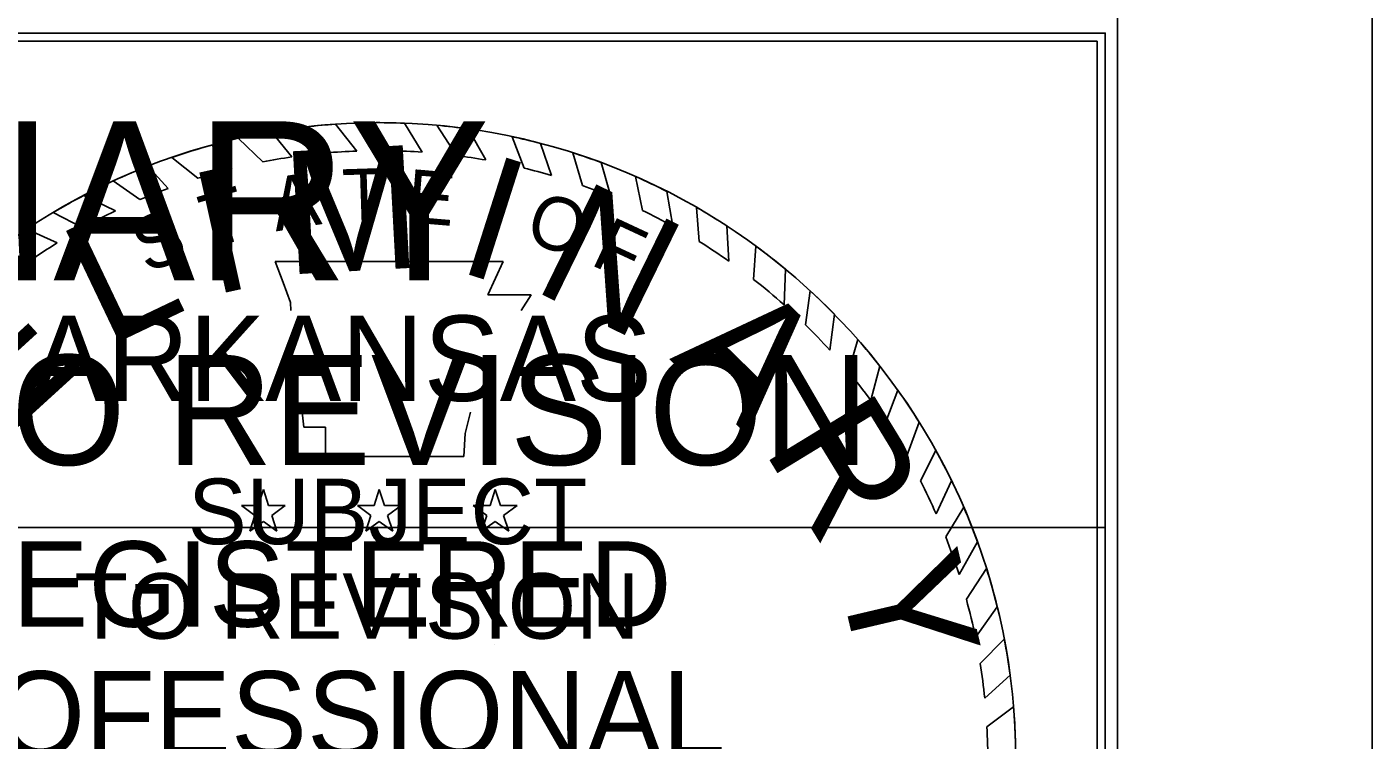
# Model space of a CAD drawing. Extents: x -0.29 to 1.42, y 0 to 0.92.
# Drawn here: x 1.3066 to 1.4167, y 0.7945 to 0.8529 of the extents above; entities that cross this region are included whole.
import ezdxf

# ---------------------------------------------------------------- set-up
doc = ezdxf.new("R2010")
doc.units = 0
for name, color, linetype in [('DSN_DRFT_Guideline-No-Plot', 7, 'Continuous'), ('SHET_Border-Lines', 7, 'Continuous'), ('SHET_Stamp-Prelim', 7, 'Continuous'), ('SHET_Stamp-Seal', 7, 'Continuous'), ('STAMP_PE_BACKGROUND', 7, 'Continuous'), ('STAMP_PE_SEAL-INFO', 7, 'Continuous'), ('STAMP_PRELIMINARY', 7, 'Continuous')]:
    doc.layers.add(name, color=color, linetype=linetype)

msp = doc.modelspace()

# ---------------------------------------------------------------- linework, layer by layer
at = {"layer": 'DSN_DRFT_Guideline-No-Plot'}
msp.add_lwpolyline([(0, 0), (1.416666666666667, 0), (1.416666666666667, 0.9166666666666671), (0, 0.9166666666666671)], close=True, dxfattribs=at)
at = {"layer": 'SHET_Border-Lines'}
msp.add_lwpolyline([(0.02083333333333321, 0.02083333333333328), (1.3958333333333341, 0.02083333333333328), (1.3958333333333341, 0.8958333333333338), (0.02083333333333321, 0.8958333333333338)], close=True, dxfattribs=at)
at = {"layer": 'SHET_Stamp-Prelim'}
msp.add_lwpolyline([(1.2136619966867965, 0.8119287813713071), (1.3948333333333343, 0.8119287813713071), (1.3948333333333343, 0.8523810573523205), (1.2136619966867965, 0.8523810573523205)], close=True, dxfattribs=at)
at = {"layer": 'SHET_Stamp-Seal'}
msp.add_line((1.3448333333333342, 0.8023810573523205), (1.3448333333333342, 0.8023810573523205), dxfattribs=at)
msp.add_lwpolyline([(1.2948333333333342, 0.7523810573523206), (1.3948333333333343, 0.7523810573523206), (1.3948333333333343, 0.8523810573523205), (1.2948333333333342, 0.8523810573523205)], close=True, dxfattribs=at)
at = {"layer": 'STAMP_PE_BACKGROUND'}
msp.add_lwpolyline([(1.3941666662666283, 0.8517143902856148), (1.2749999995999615, 0.8517143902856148), (1.2749999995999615, 0.7325477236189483), (1.3941666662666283, 0.7325477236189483)], close=True, dxfattribs=at)
msp.add_lwpolyline([(1.3941666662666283, 0.8517143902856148), (1.2749999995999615, 0.8517143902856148), (1.2749999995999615, 0.7325477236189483), (1.3941666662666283, 0.7325477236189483)], close=True, dxfattribs=at)
at = {"layer": 'STAMP_PE_SEAL-INFO'}
for p, q in [((1.3294739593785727, 0.8447075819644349), (1.3310448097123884, 0.8425694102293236)), ((1.3294739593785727, 0.8447075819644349), (1.3310448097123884, 0.8425694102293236)), ((1.3335830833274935, 0.8427279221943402), (1.3318396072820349, 0.8449247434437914)), ((1.3335830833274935, 0.8427279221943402), (1.3318396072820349, 0.8449247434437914)), ((1.3363642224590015, 0.8427526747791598), (1.3348070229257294, 0.8450441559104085)), ((1.3363642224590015, 0.8427526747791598), (1.3348070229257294, 0.8450441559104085)), ((1.338922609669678, 0.8426381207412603), (1.337479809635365, 0.8450068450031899)), ((1.338922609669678, 0.8426381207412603), (1.337479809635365, 0.8450068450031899)), ((1.3417476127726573, 0.8423576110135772), (1.3401157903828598, 0.8448353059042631)), ((1.3417476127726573, 0.8423576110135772), (1.3401157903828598, 0.8448353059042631)), ((1.3441268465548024, 0.8419940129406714), (1.342689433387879, 0.8445374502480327)), ((1.3441268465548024, 0.8419940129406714), (1.342689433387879, 0.8445374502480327)), ((1.3238985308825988, 0.843758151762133), (1.3258868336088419, 0.8418413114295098)), ((1.3238985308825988, 0.843758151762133), (1.3258868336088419, 0.8418413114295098)), ((1.3265941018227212, 0.8442950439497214), (1.3282642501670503, 0.8422453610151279)), ((1.3265941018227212, 0.8442950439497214), (1.3282642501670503, 0.8422453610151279)), ((1.3472684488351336, 0.8413307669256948), (1.346296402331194, 0.8438987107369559)), ((1.3472684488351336, 0.8413307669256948), (1.346296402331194, 0.8438987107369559)), ((1.3495119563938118, 0.8407251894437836), (1.348622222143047, 0.843345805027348)), ((1.3495119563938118, 0.8407251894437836), (1.348622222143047, 0.843345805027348)), ((1.3184297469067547, 0.8421997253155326), (1.3205571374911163, 0.8404929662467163)), ((1.3184297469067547, 0.8421997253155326), (1.3205571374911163, 0.8404929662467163)), ((1.3217312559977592, 0.8432175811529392), (1.3233399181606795, 0.841275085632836)), ((1.3217312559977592, 0.8432175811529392), (1.3233399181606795, 0.841275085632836)), ((1.352036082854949, 0.8399065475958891), (1.3512467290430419, 0.8425837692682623)), ((1.352036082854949, 0.8399065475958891), (1.3512467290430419, 0.8425837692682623)), ((1.3164868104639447, 0.8414858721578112), (1.3181331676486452, 0.8396661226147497)), ((1.3164868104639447, 0.8414858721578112), (1.3181331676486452, 0.8396661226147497)), ((1.3543729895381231, 0.8390125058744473), (1.3535662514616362, 0.8417830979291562)), ((1.3543729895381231, 0.8390125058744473), (1.3535662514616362, 0.8417830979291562)), ((1.3136506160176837, 0.8402815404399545), (1.3158266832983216, 0.8387465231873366)), ((1.3136506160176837, 0.8402815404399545), (1.3158266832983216, 0.8387465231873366)), ((1.356950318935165, 0.8378650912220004), (1.3563760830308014, 0.8406443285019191)), ((1.356950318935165, 0.8378650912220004), (1.3563760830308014, 0.8406443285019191)), ((1.3112428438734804, 0.8390978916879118), (1.3138318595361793, 0.8378405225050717)), ((1.3112428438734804, 0.8390978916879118), (1.3138318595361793, 0.8378405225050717)), ((1.3594403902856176, 0.8365835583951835), (1.3589543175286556, 0.8394256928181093)), ((1.3594403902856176, 0.8365835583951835), (1.3589543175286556, 0.8394256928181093)), ((1.3616057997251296, 0.8353188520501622), (1.3613841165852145, 0.8381126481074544)), ((1.3616057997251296, 0.8353188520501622), (1.3613841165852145, 0.8381126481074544)), ((1.3087400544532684, 0.8376972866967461), (1.3111542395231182, 0.8364512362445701)), ((1.3087400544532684, 0.8376972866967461), (1.3111542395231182, 0.8364512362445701)), ((1.3065791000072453, 0.8363356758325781), (1.3090468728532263, 0.8352066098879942)), ((1.3065791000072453, 0.8363356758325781), (1.3090468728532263, 0.8352066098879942)), ((1.3640334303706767, 0.8337179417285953), (1.3638592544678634, 0.8365957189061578)), ((1.3640334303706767, 0.8337179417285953), (1.3638592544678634, 0.8365957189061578)), ((1.304230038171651, 0.834845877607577), (1.3067758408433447, 0.8337010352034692)), ((1.304230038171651, 0.834845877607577), (1.3067758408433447, 0.8337010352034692)), ((1.3660478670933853, 0.8322263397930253), (1.3662390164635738, 0.8349483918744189)), ((1.3660478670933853, 0.8322263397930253), (1.3662390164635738, 0.8349483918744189)), ((1.3268852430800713, 0.8336989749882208), (1.3455681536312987, 0.8336989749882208)), ((1.3275632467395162, 0.831981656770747), (1.3268852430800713, 0.8336989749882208)), ((1.3268852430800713, 0.8336989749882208), (1.3455681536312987, 0.8336989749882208)), ((1.3275632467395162, 0.831981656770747), (1.3268852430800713, 0.8336989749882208)), ((1.3455681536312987, 0.8336989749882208), (1.3443118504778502, 0.8309512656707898)), ((1.3455681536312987, 0.8336989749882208), (1.3443118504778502, 0.8309512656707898)), ((1.3685422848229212, 0.8301458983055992), (1.368651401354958, 0.833065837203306)), ((1.3685422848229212, 0.8301458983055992), (1.368651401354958, 0.833065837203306)), ((1.3281440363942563, 0.830318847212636), (1.3275632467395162, 0.831981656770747)), ((1.3281440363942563, 0.830318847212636), (1.3275632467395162, 0.831981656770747)), ((1.3702883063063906, 0.8285135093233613), (1.370675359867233, 0.8312984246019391)), ((1.3702883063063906, 0.8285135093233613), (1.370675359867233, 0.8312984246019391)), ((1.3281841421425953, 0.8296795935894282), (1.3281440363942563, 0.830318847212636)), ((1.3281841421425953, 0.8296795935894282), (1.3281440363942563, 0.830318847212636)), ((1.3443118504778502, 0.8309512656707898), (1.3478453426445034, 0.8309512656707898)), ((1.3443118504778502, 0.8309512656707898), (1.3478453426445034, 0.8309512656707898)), ((1.3478453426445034, 0.8309512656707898), (1.3470357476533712, 0.8296795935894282)), ((1.3478453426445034, 0.8309512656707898), (1.3470357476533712, 0.8296795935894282)), ((1.3722943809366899, 0.8264278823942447), (1.37266661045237, 0.8293665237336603)), ((1.3722943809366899, 0.8264278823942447), (1.37266661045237, 0.8293665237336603)), ((1.3738243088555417, 0.8246601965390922), (1.374586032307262, 0.8272927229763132)), ((1.3738243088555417, 0.8246601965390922), (1.374586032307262, 0.8272927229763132)), ((1.3756344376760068, 0.8223293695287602), (1.3763889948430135, 0.82511935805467)), ((1.3756344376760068, 0.8223293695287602), (1.3763889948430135, 0.82511935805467)), ((1.376862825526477, 0.8205685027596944), (1.3778557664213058, 0.8231570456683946)), ((1.376862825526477, 0.8205685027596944), (1.3778557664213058, 0.8231570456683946)), ((1.3292525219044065, 0.8201321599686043), (1.3291057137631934, 0.8213470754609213)), ((1.3292525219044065, 0.8201321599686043), (1.3291057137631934, 0.8213470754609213)), ((1.3428700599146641, 0.8213470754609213), (1.3424349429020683, 0.8196169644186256)), ((1.3428700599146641, 0.8213470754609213), (1.3424349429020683, 0.8196169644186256)), ((1.378584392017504, 0.8177901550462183), (1.379604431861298, 0.8205345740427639)), ((1.378584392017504, 0.8177901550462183), (1.379604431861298, 0.8205345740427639)), ((1.331008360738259, 0.8201321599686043), (1.3292525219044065, 0.8201321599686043)), ((1.331008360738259, 0.8201321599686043), (1.3292525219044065, 0.8201321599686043)), ((1.331008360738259, 0.8177279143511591), (1.331008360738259, 0.8201321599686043)), ((1.331008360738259, 0.8177279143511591), (1.331008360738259, 0.8201321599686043)), ((1.3424349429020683, 0.8196169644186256), (1.3423475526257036, 0.8177279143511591)), ((1.3424349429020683, 0.8196169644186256), (1.3423475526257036, 0.8177279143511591)), ((1.3796987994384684, 0.815742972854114), (1.380964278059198, 0.8182248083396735)), ((1.3796987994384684, 0.815742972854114), (1.380964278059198, 0.8182248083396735)), ((1.3423475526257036, 0.8177279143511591), (1.331008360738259, 0.8177279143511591)), ((1.3423475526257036, 0.8177279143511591), (1.331008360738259, 0.8177279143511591)), ((1.3255072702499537, 0.8137223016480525), (1.3259305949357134, 0.8150251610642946)), ((1.3255072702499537, 0.8137223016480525), (1.3259305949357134, 0.8150251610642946)), ((1.3259305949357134, 0.8150251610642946), (1.326353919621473, 0.8137223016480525)), ((1.3259305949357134, 0.8150251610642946), (1.326353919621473, 0.8137223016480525)), ((1.3349933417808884, 0.8137223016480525), (1.3354166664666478, 0.8150251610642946)), ((1.3349933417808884, 0.8137223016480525), (1.3354166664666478, 0.8150251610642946)), ((1.3354166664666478, 0.8150251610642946), (1.3358399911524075, 0.8137223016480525)), ((1.3354166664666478, 0.8150251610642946), (1.3358399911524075, 0.8137223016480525)), ((1.344479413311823, 0.8137223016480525), (1.3449027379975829, 0.8150251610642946)), ((1.344479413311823, 0.8137223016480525), (1.3449027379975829, 0.8150251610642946)), ((1.3449027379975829, 0.8150251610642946), (1.345326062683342, 0.8137223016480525)), ((1.3449027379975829, 0.8150251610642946), (1.345326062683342, 0.8137223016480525)), ((1.380988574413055, 0.813038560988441), (1.3822531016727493, 0.815746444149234)), ((1.380988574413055, 0.813038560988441), (1.3822531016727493, 0.815746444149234)), ((1.3252456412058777, 0.812917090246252), (1.3241373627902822, 0.8137223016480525)), ((1.3241373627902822, 0.8137223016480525), (1.325507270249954, 0.8137223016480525)), ((1.3252456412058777, 0.812917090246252), (1.3241373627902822, 0.8137223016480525)), ((1.3241373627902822, 0.8137223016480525), (1.325507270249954, 0.8137223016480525)), ((1.326353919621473, 0.8137223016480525), (1.327723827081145, 0.8137223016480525)), ((1.326353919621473, 0.8137223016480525), (1.327723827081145, 0.8137223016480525)), ((1.327723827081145, 0.8137223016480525), (1.326615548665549, 0.812917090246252)), ((1.327723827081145, 0.8137223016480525), (1.326615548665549, 0.812917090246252)), ((1.3347317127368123, 0.812917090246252), (1.3336234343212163, 0.8137223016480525)), ((1.3336234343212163, 0.8137223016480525), (1.3349933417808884, 0.8137223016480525)), ((1.3347317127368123, 0.812917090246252), (1.3336234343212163, 0.8137223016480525)), ((1.3336234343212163, 0.8137223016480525), (1.3349933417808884, 0.8137223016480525)), ((1.3358399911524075, 0.8137223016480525), (1.337209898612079, 0.8137223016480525)), ((1.3358399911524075, 0.8137223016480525), (1.337209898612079, 0.8137223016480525)), ((1.337209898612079, 0.8137223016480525), (1.3361016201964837, 0.812917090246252)), ((1.337209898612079, 0.8137223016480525), (1.3361016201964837, 0.812917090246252)), ((1.3442177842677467, 0.812917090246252), (1.3431095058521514, 0.8137223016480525)), ((1.3431095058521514, 0.8137223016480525), (1.344479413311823, 0.8137223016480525)), ((1.3442177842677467, 0.812917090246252), (1.3431095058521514, 0.8137223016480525)), ((1.3431095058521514, 0.8137223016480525), (1.344479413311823, 0.8137223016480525)), ((1.345326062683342, 0.8137223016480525), (1.3466959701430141, 0.8137223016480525)), ((1.345326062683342, 0.8137223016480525), (1.3466959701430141, 0.8137223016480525)), ((1.3466959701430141, 0.8137223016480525), (1.345587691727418, 0.812917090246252)), ((1.3466959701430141, 0.8137223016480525), (1.345587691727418, 0.812917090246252)), ((1.381772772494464, 0.811154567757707), (1.3832473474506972, 0.8135774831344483)), ((1.381772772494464, 0.811154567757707), (1.3832473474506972, 0.8135774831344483)), ((1.3248223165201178, 0.81161423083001), (1.3252456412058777, 0.812917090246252)), ((1.3248223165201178, 0.81161423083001), (1.3252456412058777, 0.812917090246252)), ((1.326615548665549, 0.812917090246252), (1.327038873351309, 0.81161423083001)), ((1.326615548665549, 0.812917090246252), (1.327038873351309, 0.81161423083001)), ((1.3343083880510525, 0.81161423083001), (1.3347317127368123, 0.812917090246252)), ((1.3343083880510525, 0.81161423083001), (1.3347317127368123, 0.812917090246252)), ((1.3361016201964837, 0.812917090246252), (1.3365249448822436, 0.81161423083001)), ((1.3361016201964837, 0.812917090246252), (1.3365249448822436, 0.81161423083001)), ((1.3437944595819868, 0.81161423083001), (1.3442177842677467, 0.812917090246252)), ((1.3437944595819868, 0.81161423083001), (1.3442177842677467, 0.812917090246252)), ((1.345587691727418, 0.812917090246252), (1.346011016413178, 0.81161423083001)), ((1.345587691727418, 0.812917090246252), (1.346011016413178, 0.81161423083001)), ((1.3259305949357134, 0.8124194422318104), (1.3248223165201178, 0.81161423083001)), ((1.3259305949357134, 0.8124194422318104), (1.3248223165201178, 0.81161423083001)), ((1.327038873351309, 0.81161423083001), (1.3259305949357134, 0.8124194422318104)), ((1.327038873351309, 0.81161423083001), (1.3259305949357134, 0.8124194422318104)), ((1.3354166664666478, 0.8124194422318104), (1.3343083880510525, 0.81161423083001)), ((1.3354166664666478, 0.8124194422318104), (1.3343083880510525, 0.81161423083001)), ((1.3365249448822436, 0.81161423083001), (1.3354166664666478, 0.8124194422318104)), ((1.3365249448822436, 0.81161423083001), (1.3354166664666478, 0.8124194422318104)), ((1.3449027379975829, 0.8124194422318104), (1.3437944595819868, 0.81161423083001)), ((1.3449027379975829, 0.8124194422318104), (1.3437944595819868, 0.81161423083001)), ((1.346011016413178, 0.81161423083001), (1.3449027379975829, 0.8124194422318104)), ((1.346011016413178, 0.81161423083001), (1.3449027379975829, 0.8124194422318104)), ((1.382861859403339, 0.8080880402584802), (1.3843733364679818, 0.8107384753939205)), ((1.382861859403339, 0.8080880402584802), (1.3843733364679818, 0.8107384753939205)), ((1.3834635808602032, 0.8060512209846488), (1.3851045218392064, 0.8085781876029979)), ((1.3834635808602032, 0.8060512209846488), (1.3851045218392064, 0.8085781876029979)), ((1.3842065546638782, 0.8029302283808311), (1.3859874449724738, 0.8054251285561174)), ((1.3842065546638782, 0.8029302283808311), (1.3859874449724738, 0.8054251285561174)), ((1.384592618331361, 0.8008063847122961), (1.3865668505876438, 0.8027792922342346)), ((1.384592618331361, 0.8008063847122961), (1.3865668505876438, 0.8027792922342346)), ((1.3849625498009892, 0.797962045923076), (1.3870442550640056, 0.7998393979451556)), ((1.3849625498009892, 0.797962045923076), (1.3870442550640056, 0.7998393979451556)), ((1.3851427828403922, 0.7956260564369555), (1.3873228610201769, 0.7972563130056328)), ((1.3851427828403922, 0.7956260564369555), (1.3873228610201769, 0.7972563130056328))]:
    msp.add_line(p, q, dxfattribs=at)
for radius, start, end in [(0.05208333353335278, 93.93814766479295, 96.55171575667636), (0.05208333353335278, 93.93814766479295, 96.55171575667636), (0.05208333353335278, 87.72978562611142, 90.67067134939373), (0.05208333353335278, 87.72978562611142, 90.67067134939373), (0.05208333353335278, 81.97315125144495, 84.82355346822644), (0.05208333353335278, 81.97315125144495, 84.82355346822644), (0.05208333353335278, 99.75254266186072, 102.77648138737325), (0.05208333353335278, 99.75254266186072, 102.77648138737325), (0.05208333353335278, 75.31251453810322, 77.94263429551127), (0.05208333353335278, 75.31251453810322, 77.94263429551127), (0.05208333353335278, 105.2338868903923, 109.03519250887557), (0.05208333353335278, 105.2338868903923, 109.03519250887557), (0.04979730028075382, 98.25798851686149, 101.03289140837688), (0.04979730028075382, 98.25798851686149, 101.03289140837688), (0.04979730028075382, 92.11016115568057, 95.0366553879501), (0.04979730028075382, 92.11016115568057, 95.0366553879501), (0.04979730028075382, 85.96279180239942, 88.90969519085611), (0.04979730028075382, 85.96279180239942, 88.90969519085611), (0.04979730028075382, 79.92642235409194, 82.69597271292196), (0.04979730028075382, 79.92642235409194, 82.69597271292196), (0.05208333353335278, 69.60611387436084, 72.30576523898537), (0.05208333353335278, 69.60611387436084, 72.30576523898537), (0.05208333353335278, 111.31242303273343, 114.70259160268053), (0.05208333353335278, 111.31242303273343, 114.70259160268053), (0.04979730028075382, 104.03521042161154, 107.3615463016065), (0.04979730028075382, 104.03521042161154, 107.3615463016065), (0.04979730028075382, 73.55748025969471, 76.23144174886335), (0.04979730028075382, 73.55748025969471, 76.23144174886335), (0.05208333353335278, 63.13287778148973, 66.27039835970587), (0.05208333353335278, 63.13287778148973, 66.27039835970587), (0.05208333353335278, 117.65440981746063, 120.8098782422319), (0.05208333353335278, 117.65440981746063, 120.8098782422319), (0.04979730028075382, 110.30863674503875, 113.1658795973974), (0.04979730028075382, 110.30863674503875, 113.1658795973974), (0.04979730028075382, 67.62482877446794, 70.50398398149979), (0.04979730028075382, 67.62482877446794, 70.50398398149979), (0.04979730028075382, 115.68691928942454, 119.15826889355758), (0.04979730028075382, 115.68691928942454, 119.15826889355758), (0.04979730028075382, 61.155754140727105, 64.37837449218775), (0.04979730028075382, 61.155754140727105, 64.37837449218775), (0.05208333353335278, 56.90029228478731, 60.09422987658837), (0.05208333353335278, 56.90029228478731, 60.09422987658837), (0.04979730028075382, 121.97455773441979, 125.1100085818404), (0.04979730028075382, 121.97455773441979, 125.1100085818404), (0.04979730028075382, 54.923827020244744, 58.27015777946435), (0.04979730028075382, 54.923827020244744, 58.27015777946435), (0.05208333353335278, 50.34919923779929, 53.715927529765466), (0.05208333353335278, 50.34919923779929, 53.715927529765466), (0.04979730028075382, 48.301629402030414, 52.0395271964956), (0.04979730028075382, 48.301629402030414, 52.0395271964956), (0.05208333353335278, 44.34049610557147, 47.392920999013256), (0.05208333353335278, 44.34049610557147, 47.392920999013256), (0.04979730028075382, 42.221157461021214, 45.55119386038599), (0.04979730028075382, 42.221157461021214, 45.55119386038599), (0.05208333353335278, 38.12472275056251, 41.2315730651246), (0.05208333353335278, 38.12472275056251, 41.2315730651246), (0.04979730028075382, 36.135025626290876, 39.53106373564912), (0.04979730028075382, 36.135025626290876, 39.53106373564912), (0.05208333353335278, 31.96138013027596, 35.42937309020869), (0.05208333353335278, 31.96138013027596, 35.42937309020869), (0.04979730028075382, 29.903213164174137, 33.66454441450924), (0.04979730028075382, 29.903213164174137, 33.66454441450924), (0.05208333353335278, 25.939091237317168, 29.012473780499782), (0.05208333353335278, 25.939091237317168, 29.012473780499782), (0.04979730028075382, 23.77322286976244, 27.221139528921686), (0.04979730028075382, 23.77322286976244, 27.221139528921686), (0.05208333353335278, 19.953806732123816, 23.314091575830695), (0.05208333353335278, 19.953806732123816, 23.314091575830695), (0.04979730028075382, 17.68022309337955, 21.42508660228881), (0.04979730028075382, 17.68022309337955, 21.42508660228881), (0.05208333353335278, 13.842052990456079, 17.444684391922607), (0.05208333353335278, 13.842052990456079, 17.444684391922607), (0.04979730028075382, 11.544448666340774, 15.236388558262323), (0.04979730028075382, 11.544448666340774, 15.236388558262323), (0.05208333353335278, 7.585188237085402, 10.862114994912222), (0.05208333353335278, 7.585188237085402, 10.862114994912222), (0.04979730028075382, 5.7598993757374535, 9.06055796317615), (0.04979730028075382, 5.7598993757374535, 9.06055796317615), (0.05208333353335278, 1.7215475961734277, 4.7268136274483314), (0.05208333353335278, 1.7215475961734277, 4.7268136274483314), (0.04979730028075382, 359.7328912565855, 3.0639197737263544), (0.04979730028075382, 359.7328912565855, 3.0639197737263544)]:
    msp.add_arc((1.3354166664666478, 0.7929643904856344), radius, start, end, dxfattribs=at)
at = {"layer": 'STAMP_PRELIMINARY'}
msp.add_circle((1.3354166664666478, 0.7929643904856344), 0.05208333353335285, dxfattribs=at)
msp.add_circle((1.3354166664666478, 0.7929643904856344), 0.05208333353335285, dxfattribs=at)

# ---------------------------------------------------------------- texts
at = {"layer": 'SHET_Stamp-Prelim'}
for s, height, p in [('PRELIMINARY', 0.013, (1.2266349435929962, 0.8321549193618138)), ('SUBJECT TO REVISION', 0.009, (1.239775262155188, 0.8170418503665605))]:
    msp.add_text(s, height=height, dxfattribs=at).set_placement(p)
at = {"layer": 'STAMP_PE_SEAL-INFO'}
for s, height, rotation, p in [('T', 0.0043646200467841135, 1.824794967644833, (1.3324583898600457, 0.836866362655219)), ('T', 0.0043646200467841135, 1.824794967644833, (1.3324583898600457, 0.836866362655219)), ('E', 0.004364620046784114, 355.2001929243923, (1.3375428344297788, 0.8369145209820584)), ('E', 0.004364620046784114, 355.2001929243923, (1.3375428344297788, 0.8369145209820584)), ('A', 0.004364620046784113, 9.067898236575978, (1.3269468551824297, 0.8361430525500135)), ('A', 0.004364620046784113, 9.067898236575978, (1.3269468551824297, 0.8361430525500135)), ('T', 0.004364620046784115, 16.311001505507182, (1.321570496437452, 0.8347306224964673)), ('T', 0.004364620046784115, 16.311001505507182, (1.321570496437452, 0.8347306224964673)), ('O', 0.004364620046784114, 342.25064860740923, (1.3471892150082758, 0.8353678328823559)), ('O', 0.004364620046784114, 342.25064860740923, (1.3471892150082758, 0.8353678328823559)), ('S', 0.004364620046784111, 23.55410477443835, (1.3164151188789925, 0.8326516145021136)), ('S', 0.004364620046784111, 23.55410477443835, (1.3164151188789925, 0.8326516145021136)), ('F', 0.0043646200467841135, 335.00754533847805, (1.352582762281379, 0.8334793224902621)), ('F', 0.0043646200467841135, 335.00754533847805, (1.352582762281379, 0.8334793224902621))]:
    msp.add_text(s, height=height, rotation=rotation, dxfattribs=at).set_placement(p)
for s, p in [('ARKANSAS', (1.3068814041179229, 0.8222796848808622)), ('ARKANSAS', (1.3068814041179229, 0.8222796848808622)), ('REGISTERED', (1.298637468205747, 0.8038080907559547)), ('REGISTERED', (1.298637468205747, 0.8038080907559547)), ('PROFESSIONAL', (1.2911053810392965, 0.7931852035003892)), ('PROFESSIONAL', (1.2911053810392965, 0.7931852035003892))]:
    msp.add_text(s, height=0.006983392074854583, dxfattribs=at).set_placement(p)
at = {"layer": 'STAMP_PRELIMINARY'}
for s, height, rotation, p in [('M', 0.010056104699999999, 3.107384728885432, (1.3277948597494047, 0.8326065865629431)), ('M', 0.010056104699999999, 3.107384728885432, (1.3277948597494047, 0.8326065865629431)), ('I', 0.010056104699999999, 342.3163708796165, (1.3415801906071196, 0.8329830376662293)), ('I', 0.010056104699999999, 342.3163708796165, (1.3415801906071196, 0.8329830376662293)), ('I', 0.010056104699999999, 12.524847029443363, (1.3216599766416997, 0.8308792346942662)), ('I', 0.010056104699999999, 12.524847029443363, (1.3216599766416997, 0.8308792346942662)), ('N', 0.010056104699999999, 333.93819993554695, (1.3477687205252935, 0.8314521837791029)), ('N', 0.010056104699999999, 333.93819993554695, (1.3477687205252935, 0.8314521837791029)), ('L', 0.010056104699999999, 25.513048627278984, (1.31311876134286, 0.8266382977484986)), ('L', 0.010056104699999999, 25.513048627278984, (1.31311876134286, 0.8266382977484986)), ('E', 0.010056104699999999, 42.3578427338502, (1.304835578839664, 0.8192021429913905)), ('E', 0.010056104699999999, 42.3578427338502, (1.304835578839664, 0.8192021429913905)), ('A', 0.010056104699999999, 315.65789090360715, (1.359131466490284, 0.8257233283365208)), ('A', 0.010056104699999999, 315.65789090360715, (1.359131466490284, 0.8257233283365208)), ('R', 0.010056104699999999, 301.38306156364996, (1.3667735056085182, 0.8183817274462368)), ('R', 0.010056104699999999, 301.38306156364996, (1.3667735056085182, 0.8183817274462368)), ('Y', 0.010056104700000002, 283.25926303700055, (1.3728587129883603, 0.8084007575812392)), ('Y', 0.010056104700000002, 283.25926303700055, (1.3728587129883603, 0.8084007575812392))]:
    msp.add_text(s, height=height, rotation=rotation, dxfattribs=at).set_placement(p)
for s, p in [('SUBJECT', (1.319773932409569, 0.8105587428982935)), ('SUBJECT', (1.319773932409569, 0.8105587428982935)), ('TO REVISION', (1.3104735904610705, 0.8028228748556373)), ('TO REVISION', (1.3104735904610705, 0.8028228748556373))]:
    msp.add_text(s, height=0.005363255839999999, dxfattribs=at).set_placement(p)

doc.saveas('drawing.dxf')
